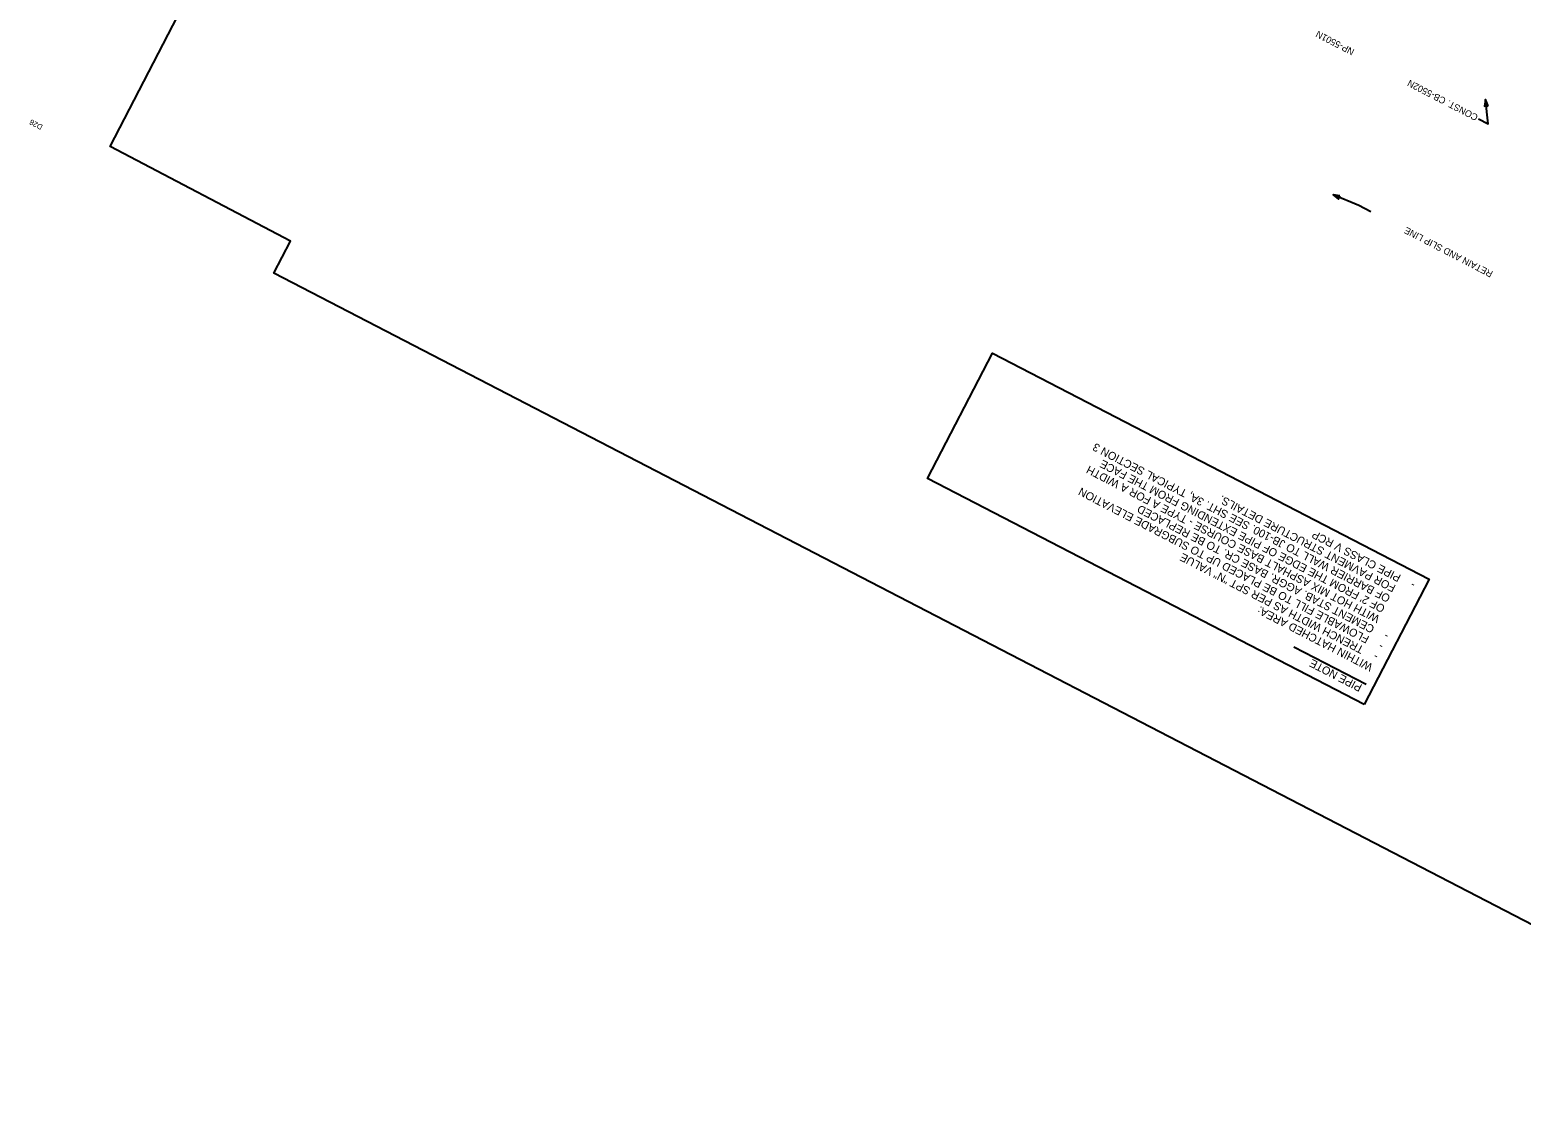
# Model space of a CAD drawing. Extents: x 1606408 to 1608529, y 1094514 to 1096115.
# Drawn here: x 1606408 to 1607526, y 1094514 to 1095316 of the extents above; entities that cross this region are included whole.
import ezdxf

# ---------------------------------------------------------------- set-up
doc = ezdxf.new("R2010")
doc.units = 0
for name, color, linetype in [('RD_HC_TX_Sta50', 7, 'Continuous'), ('RD_PD_PatLn6', 7, 'Continuous'), ('RD_Sketch9', 7, 'Continuous')]:
    doc.layers.add(name, color=color, linetype=linetype)

msp = doc.modelspace()

# ---------------------------------------------------------------- linework, layer by layer
at = {"layer": 'RD_HC_TX_Sta50'}
msp.add_lwpolyline([(1607787.2, 1094514.3), (1606590.9, 1095133.7), (1606603.3, 1095157.8), (1606468, 1095228.7), (1606883.8, 1096031.8), (1608215.8, 1095342.1)], close=True, dxfattribs=at)
msp.add_lwpolyline([(1607787.2, 1094514.3), (1606590.9, 1095133.7), (1606603.3, 1095157.8), (1606468, 1095228.7), (1606883.8, 1096031.8), (1608215.8, 1095342.1)], close=True, dxfattribs=at)
msp.add_lwpolyline([(1607787.2, 1094514.3), (1606590.9, 1095133.7), (1606603.3, 1095157.8), (1606468, 1095228.7), (1606883.8, 1096031.8), (1608215.8, 1095342.1)], close=True, dxfattribs=at)
msp.add_lwpolyline([(1607787.2, 1094514.3), (1606590.9, 1095133.7), (1606603.3, 1095157.8), (1606468, 1095228.7), (1606883.8, 1096031.8), (1608215.8, 1095342.1)], close=True, dxfattribs=at)
msp.add_lwpolyline([(1607787.2, 1094514.3), (1606590.9, 1095133.7), (1606603.3, 1095157.8), (1606468, 1095228.7), (1606883.8, 1096031.8), (1608215.8, 1095342.1)], close=True, dxfattribs=at)
msp.add_lwpolyline([(1607787.2, 1094514.3), (1606590.9, 1095133.7), (1606603.3, 1095157.8), (1606468, 1095228.7), (1606883.8, 1096031.8), (1608215.8, 1095342.1)], close=True, dxfattribs=at)
at = {"layer": 'RD_Sketch9'}
msp.add_line((1607410.1, 1094825.3), (1607355.8, 1094853.4), dxfattribs=at)
for points in [[(1607494.3, 1095249.5), (1607501.6, 1095245.7), (1607499.7, 1095263.9)], [(1607413.6, 1095179.7), (1607404.5, 1095184.4), (1607385.4, 1095192.4)]]:
    msp.add_lwpolyline(points, dxfattribs=at)
for points in [[(1607501.5, 1095259.2), (1607499.7, 1095263.9), (1607498.9, 1095259)], [(1607390.3, 1095191.7), (1607385.4, 1095192.4), (1607389.3, 1095189.3)], [(1607408.7, 1094810.3), (1607081.2, 1094979.9), (1607129.8, 1095073.8), (1607457.3, 1094904.2)]]:
    msp.add_lwpolyline(points, close=True, dxfattribs=at)

# ---------------------------------------------------------------- texts
at = {"layer": 'RD_PD_PatLn6'}
msp.add_text('D28', height=4, rotation=152.6268, dxfattribs=at).set_placement((1606417.9, 1095244.6))
at = {"layer": 'RD_Sketch9'}
for s, height, p in [('NP-5501N', 5, (1607401.7, 1095301.4)), ('CONST. CB-5502N', 5, (1607494.5, 1095252.2)), ('RETAIN AND SLIP LINE', 5, (1607505.6, 1095134.8)), ('OF BARRIER WALL TO JB-100. SEE SHT. 3A, TYPICAL SECTION 3', 6, (1607428.8, 1094891.8)), ("OF 2' FROM THE EDGE OF PIPE EXTENDING FROM THE FACE", 6, (1607424.8, 1094884.1)), ('WITH HOT MIX ASPHALT BASE COURSE - TYPE A FOR A WIDTH', 6, (1607420.8, 1094876.5)), ('FLOWABLE FILL TO BE PLACED UP TO SUBGRADE ELEVATION', 6, (1607412.9, 1094861.1)), ('CEMENT STAB. AGGR. BASE CR. TO BE REPLACED', 6, (1607416.9, 1094868.8)), ('FOR PAVMENT STRUCTURE DETAILS.', 6, (1607432.8, 1094899.5)), ('PIPE CLASS V RCP', 6, (1607436.7, 1094907.2)), ('TRENCH WIDTH AS PER SPT "N" VALUE', 6, (1607408.9, 1094853.4)), ('-', 6, (1607447.4, 1094901.6)), ('WITHIN HATCHED AREA:', 6, (1607415.6, 1094840.2)), ('-', 6, (1607427.5, 1094863.3)), ('-', 6, (1607419.6, 1094847.9)), ('-', 6, (1607423.5, 1094855.6)), ('PIPE NOTE', 6, (1607407.6, 1094824.9))]:
    msp.add_text(s, height=height, rotation=152.6268, dxfattribs=at).set_placement(p)

doc.saveas('drawing.dxf')
